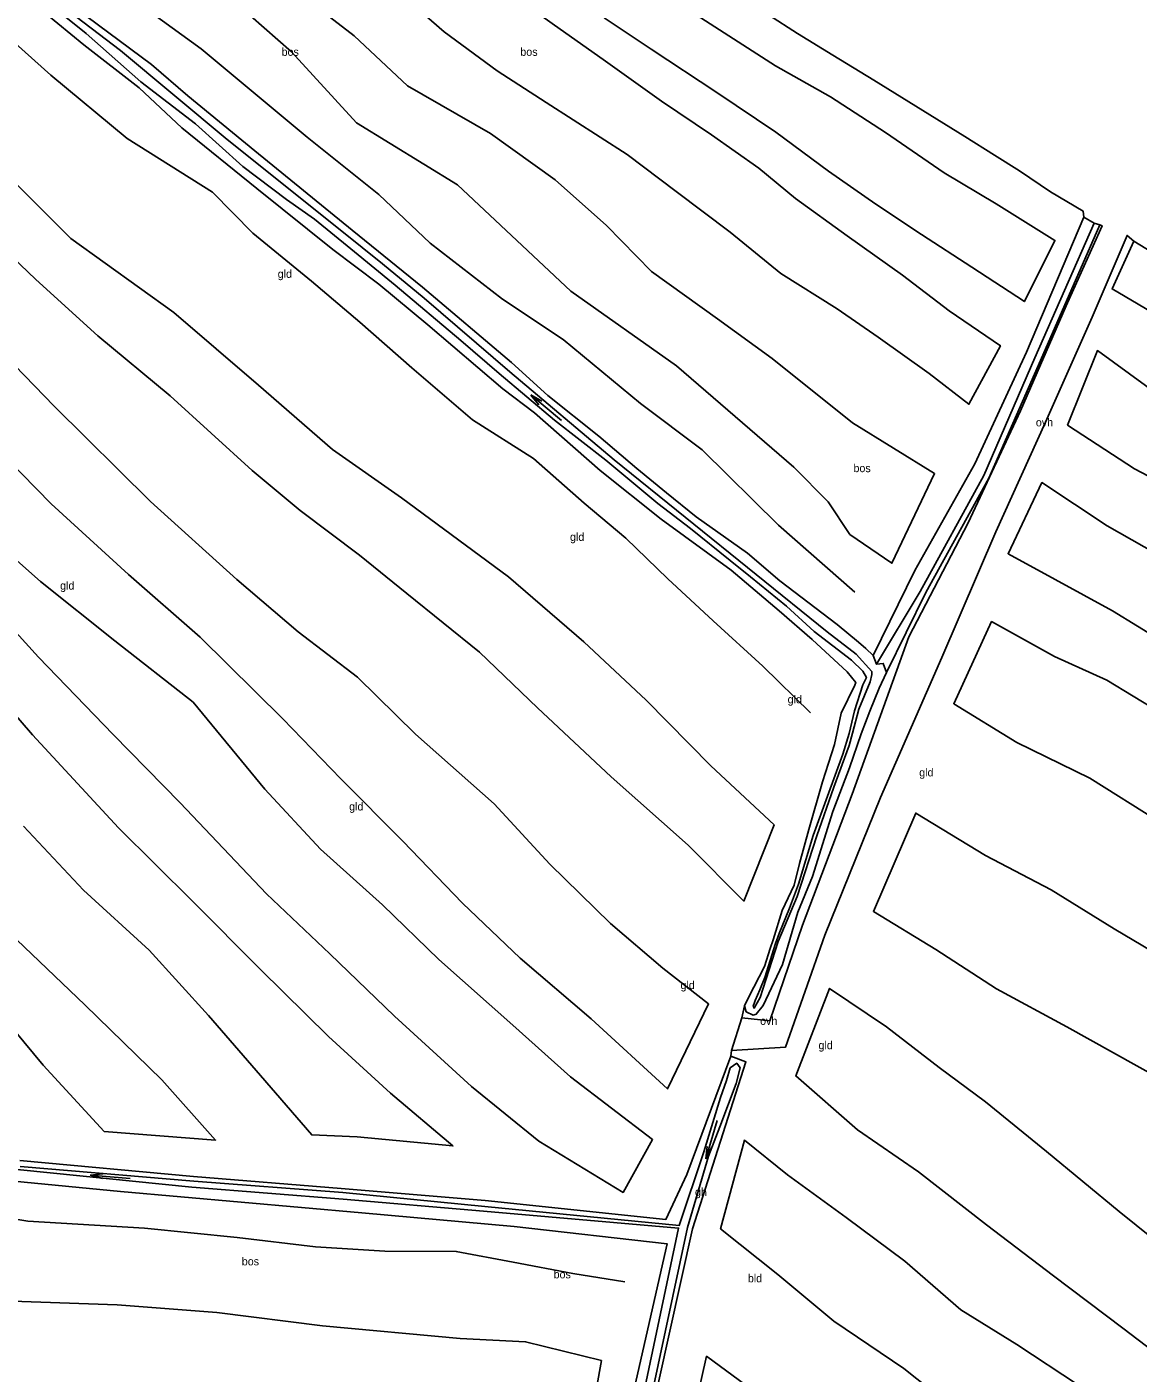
# Model space of a CAD drawing. Extents: x 154825 to 158680, y 370717 to 378075.
# Drawn here: x 155737.7 to 155876.6, y 376911 to 377079.3 of the extents above; entities that cross this region are included whole.
import ezdxf

# ---------------------------------------------------------------- set-up
doc = ezdxf.new("R2010")
doc.units = 0
for name, color, linetype in [('bos(vs)', 7, 'Continuous'), ('bouwland_akkerland(vs)', 7, 'Continuous'), ('breuklijn', 7, 'Continuous'), ('cultuurscheiding', 7, 'Continuous'), ('gashouder punt', 7, 'Continuous'), ('grasland_productiegrasl(vs)', 7, 'Continuous'), ('greppel - midden sloot', 7, 'Continuous'), ('hoogteverschillijn', 7, 'Continuous'), ('insteek sloot', 7, 'Continuous'), ('maaiveldlijn algemeen - onverhard', 7, 'Continuous'), ('onverhard(vs)', 7, 'Continuous'), ('Sloot bodem', 7, 'Continuous'), ('stroomrichting  watergangen', 7, 'Continuous'), ('vlak_akkerland', 7, 'Continuous'), ('vlak_Bos', 7, 'Continuous'), ('vlak_Grasland', 7, 'Continuous'), ('vlak_Grazige_vegetatie', 7, 'Continuous')]:
    doc.layers.add(name, color=color, linetype=linetype)

msp = doc.modelspace()

# ---------------------------------------------------------------- linework, layer by layer
at = {"layer": 'bos(vs)'}
msp.add_lwpolyline([(155869.81, 377055.5), (155862.64, 377038.62), (155856.17, 377024.64), (155848.67, 377011.32), (155843.45, 377000.7)], dxfattribs=at)
at = {"layer": 'breuklijn'}
msp.add_lwpolyline([(155833.53, 377024.24), (155818.9, 377036.91), (155805.68, 377046.23), (155791.49, 377059.51), (155778.9, 377067.29), (155770.76, 377076.15), (155760.52, 377085.18), (155747.44, 377094.53), (155734.38, 377105.71), (155721.14, 377112.94), (155709.6, 377124.17), (155697.1, 377135.78)], dxfattribs=at)
at = {"layer": 'cultuurscheiding'}
for points in [[(155827.37, 376956.92), (155827.05, 376955.41)], [(155825.68, 376950.6), (155825.74, 376951.3)]]:
    msp.add_lwpolyline(points, dxfattribs=at)
at = {"layer": 'greppel - midden sloot'}
msp.add_lwpolyline([(155871.07, 377054.75), (155863.69, 377037.88), (155857.29, 377023.21), (155849.35, 377008.68), (155843.89, 376999.6)], dxfattribs=at)
at = {"layer": 'hoogteverschillijn'}
for points in [[(155697.1, 377135.78), (155691.31, 377130.54), (155696.85, 377125.96), (155701.48, 377121.9), (155706.84, 377117.55), (155713.41, 377111.67), (155721.11, 377105.34), (155731.41, 377097.58), (155740.31, 377090.57), (155748.11, 377084.79), (155759.45, 377076.54), (155772.71, 377065.49), (155781.66, 377058.32), (155788.1, 377052.22), (155797.13, 377045.23), (155804.7, 377040.21), (155814.37, 377032.18), (155822.07, 377026.41), (155831.61, 377016.98), (155841.16, 377008.6)], [(155767.02, 377087.11), (155778.59, 377078.15), (155785.27, 377071.88), (155795.62, 377065.94), (155803.72, 377060.15), (155810.13, 377054.43), (155815.76, 377048.69), (155824.02, 377042.77), (155830.85, 377037.83), (155840.88, 377029.79), (155851.15, 377023.44), (155845.81, 377012.22), (155840.55, 377015.83), (155837.84, 377019.89), (155833.53, 377024.24)], [(155799.45, 377082.46), (155804.35, 377078.99), (155809.73, 377075.17), (155816.99, 377069.97), (155823.24, 377065.77), (155829.16, 377061.62), (155833.77, 377057.8), (155840.22, 377053.13), (155847.15, 377048.23), (155852.98, 377043.79), (155859.36, 377039.41), (155855.43, 377032.09), (155850.48, 377035.95), (155844.09, 377040.47), (155838.98, 377044.02), (155831.93, 377048.43), (155825.6, 377053.6), (155818.85, 377058.71), (155812.73, 377063.33), (155802.59, 377069.82), (155796.48, 377073.78), (155789.83, 377078.64), (155784.46, 377083.35)], [(155835.61, 376993.53), (155829.68, 376999.35), (155823.48, 377005.03), (155817.8, 377010.29), (155812.54, 377015.35), (155807.35, 377019.73), (155801.01, 377025.32), (155793.36, 377030.15), (155785.81, 377036.65), (155779.31, 377042.35), (155773.27, 377047.48), (155765.94, 377053.47), (155760.89, 377058.59), (155750.23, 377065.33), (155740.69, 377073.24), (155732.59, 377080.46)], [(155820.75, 377081.15), (155831.25, 377074.41), (155838.14, 377070.52), (155844.99, 377066.08), (155852.32, 377061.04), (155858.85, 377057.15), (155866.18, 377052.57), (155862.38, 377044.94), (155855.8, 377049.23), (155849.51, 377053.31), (155843.78, 377057.11), (155837.9, 377061.22), (155831.31, 377066.11), (155823.92, 377071.07), (155815.73, 377076.48), (155809.85, 377080.39)], [(155869.7, 377056.25), (155865.65, 377058.65), (155861.75, 377061.26), (155858.65, 377063.23), (155854.93, 377065.56), (155843.54, 377072.61), (155838.44, 377075.73), (155833.99, 377078.46), (155830.39, 377080.78)], [(155735.71, 377060.29), (155743.17, 377052.83), (155756.06, 377043.55), (155766.65, 377034.5), (155775.88, 377026.43), (155784.51, 377020.42), (155797.89, 377010.51), (155807.29, 377002.42), (155815.1, 376995.1), (155823.16, 376986.91), (155831.08, 376979.54), (155827.31, 376969.99), (155820.33, 376976.97), (155810.73, 376985.52), (155801.49, 376994.16), (155794.24, 377001.09), (155785.18, 377008.46), (155779.24, 377013.23), (155771.85, 377018.8), (155765.85, 377023.82), (155755.6, 377033.17), (155746.54, 377040.66), (155738.81, 377047.69), (155731.88, 377054.28)], [(155879.06, 377050.63), (155876.03, 377052.47), (155873.33, 377046.52), (155878.21, 377043.67)], [(155734.93, 377038.24), (155741.1, 377031.86), (155753.11, 377019.93), (155763.92, 377010.19), (155771.59, 377003.65), (155779.02, 376998), (155786.24, 376990.86), (155796.09, 376982.17), (155803.04, 376974.6), (155810.63, 376967.2), (155817.17, 376961.59), (155822.9, 376957.14), (155817.74, 376946.51), (155808.23, 376955.28), (155799.33, 376962.84), (155792.14, 376969.75), (155784.67, 376977.47), (155776.93, 376985.28), (155769.68, 376992.77), (155759.35, 377002.99), (155750.38, 377010.82), (155740.7, 377019.63), (155733.2, 377027.26)], [(155879.49, 377033), (155871.49, 377038.8), (155867.77, 377029.49), (155876.13, 377024.01), (155884.02, 377019.91)], [(155878.86, 377013.4), (155872.7, 377016.9), (155864.55, 377022.3), (155860.32, 377013.42), (155866.21, 377010.19), (155873.37, 377006.29), (155879.62, 377002.46)], [(155732.25, 377016.24), (155739.38, 377009.93), (155748.68, 377002.54), (155758.45, 376994.84), (155767.43, 376983.98), (155774.37, 376976.47), (155782.11, 376969.51), (155789.17, 376962.7), (155798.41, 376954.5), (155805.62, 376948.04), (155815.89, 376940.19), (155812.21, 376933.59), (155801.66, 376939.99), (155793.25, 376946.83), (155783.61, 376955.61), (155775.54, 376963.42), (155767.61, 376970.92), (155756.85, 376982.29), (155748.48, 376990.81), (155739.14, 377000.5), (155730.23, 377010.27)], [(155879.25, 376993.63), (155872.66, 376997.6), (155866.11, 377000.57), (155858.27, 377004.94), (155853.54, 376994.66), (155861.43, 376989.82), (155870.56, 376985.38), (155879.17, 376979.96)], [(155729.32, 377001.24), (155738.37, 376990.76), (155749.13, 376979.15), (155758.4, 376969.99), (155766.88, 376961.46), (155775.4, 376953.05), (155783.15, 376946), (155790.93, 376939.4), (155778.98, 376940.53), (155773.29, 376940.77), (155766.86, 376948.21), (155760.36, 376955.7), (155752.98, 376963.87), (155744.75, 376971.34), (155737.24, 376979.34)], [(155883.21, 376960.83), (155873.58, 376966.54), (155865.73, 376971.4), (155857.49, 376975.7), (155848.78, 376980.99), (155843.49, 376968.71), (155851.31, 376963.95), (155858.88, 376959.02), (155867.66, 376954.27), (155879.33, 376947.79)], [(155735.47, 376966.05), (155744.93, 376957.01), (155754.54, 376947.64), (155761.27, 376940.12), (155747.34, 376941.2), (155739.72, 376949.49), (155732.61, 376957.99)], [(155907.78, 376907.73), (155899.49, 376913.63), (155888.89, 376919.42), (155874.21, 376931.2), (155865.14, 376938.69), (155857.52, 376944.89), (155851.7, 376949.19), (155845.11, 376954.26), (155838.01, 376959.07), (155833.79, 376948.15), (155841.49, 376941.39), (155849.14, 376936.16), (155857.64, 376929.53), (155866.01, 376923.17), (155874.66, 376916.61), (155883.38, 376909.98)], [(155869.11, 376909.47), (155861.42, 376914.58), (155854.44, 376918.9), (155847.41, 376924.97), (155840.1, 376930.44), (155832.77, 376935.79), (155827.36, 376940.1), (155824.39, 376929.03), (155831.55, 376923.31), (155838.56, 376917.48), (155847.28, 376911.58), (155854.99, 376905.45)], [(155812.44, 376922.41), (155805.92, 376923.46), (155798.45, 376924.88), (155791.34, 376926.2), (155782.44, 376926.22), (155773.74, 376926.77), (155763.95, 376927.94), (155752.36, 376929.1), (155737.8, 376930), (155727.39, 376931.69), (155714.44, 376932.41), (155715.02, 376921.27), (155724.5, 376920.22), (155735.85, 376920), (155748.95, 376919.52), (155761.41, 376918.57), (155774.63, 376916.91), (155791.83, 376915.32), (155800.02, 376914.91), (155809.5, 376912.57), (155807.56, 376901.73)], [(155830.7, 376907.17), (155822.64, 376913.11), (155819.68, 376899.92)]]:
    msp.add_lwpolyline(points, dxfattribs=at)
at = {"layer": 'insteek sloot'}
for points in [[(155743.87, 377081.52), (155753.26, 377074.56), (155757.79, 377070.65), (155766.18, 377063.78), (155778.33, 377053.87), (155787.15, 377046.73), (155798.27, 377037.3), (155802.78, 377033.18), (155809.16, 377028.12), (155813.94, 377024.06), (155817.61, 377021.03), (155821.34, 377018.04), (155827.74, 377013.47), (155831.8, 377010.02), (155838.96, 377004.58), (155841.63, 377002.38), (155842.54, 377001.57), (155843.45, 377000.7), (155843.89, 376999.6), (155844.73, 376999.71), (155845.15, 376998.56), (155844.21, 376996.6), (155843.04, 376993.74), (155841.95, 376990.9), (155840.52, 376986.64), (155838.41, 376981.21), (155835.9, 376973.07), (155834.06, 376968.63), (155832.12, 376962.05), (155829.72, 376956.93), (155828.85, 376955.85), (155828.47, 376955.74), (155827.6, 376956.17), (155827.37, 376956.92), (155827.88, 376957.93), (155829.87, 376961.81), (155830.59, 376964.08), (155830.98, 376965.14), (155832.1, 376968.81), (155833.57, 376972), (155834.25, 376974.7), (155835.42, 376978.94), (155837.15, 376984.91), (155838.64, 376989.58), (155839.45, 376993.47), (155841.17, 376996.98), (155841.29, 376997.33), (155840.22, 376998.65), (155835.84, 377002.71), (155831.73, 377006.28), (155825.73, 377011.34), (155816.97, 377017.74), (155809.35, 377023.83), (155801.12, 377031.03), (155797.19, 377034.01), (155787.81, 377042.02), (155781.66, 377047.12), (155775.92, 377051.46), (155766.43, 377059.07), (155757.04, 377066.66), (155751.72, 377071.63), (155744.79, 377077.03), (155738.29, 377082.35)], [(155871.8, 377054.54), (155864.37, 377037.55), (155857.91, 377022.85), (155850.06, 377008.57), (155845.15, 376998.56)], [(155736.8, 376937.56), (155758.52, 376935.55), (155776.96, 376934.08), (155794.97, 376932.55), (155817.55, 376930.2), (155820.17, 376935.81), (155825.68, 376950.6)], [(155951.48, 376912.04), (155950.81, 376910.1), (155944.24, 376887.93), (155932.69, 376850.87), (155927.1, 376832.28), (155925.6, 376832.14), (155908.83, 376834.69), (155899.86, 376836), (155880.29, 376838.49), (155852.58, 376842.4), (155830.69, 376845.17), (155807.49, 376848.44), (155806.69, 376849.7), (155808.97, 376866.31), (155812.21, 376885.55), (155815.22, 376903.44), (155820.87, 376929.02), (155827.55, 376949.9), (155825.68, 376950.6)], [(155710.74, 376938.93), (155711.93, 376937.32), (155749.4, 376933.71), (155779.55, 376931.02), (155798.58, 376929.34), (155817.7, 376927.17), (155811.74, 376900.95), (155807.72, 376874.51), (155804.24, 376845.73)]]:
    msp.add_lwpolyline(points, dxfattribs=at)
at = {"layer": 'maaiveldlijn algemeen - onverhard'}
for points in [[(155872.1, 377054.39), (155867.58, 377044.41), (155861.89, 377031.28), (155855.34, 377017.29), (155847.93, 377003.04), (155840.83, 376983.36), (155834.63, 376966.99), (155830.55, 376955.02), (155827.05, 376955.41)], [(155825.74, 376951.3), (155832.51, 376951.75), (155837.41, 376965.73), (155844.38, 376982.94), (155852.04, 377000.43), (155858.8, 377016.15), (155865.02, 377029.84), (155870.85, 377043), (155875.21, 377053.21)], [(155827.05, 376955.41), (155825.74, 376951.3)]]:
    msp.add_lwpolyline(points, dxfattribs=at)
at = {"layer": 'Sloot bodem'}
for points in [[(155739, 377083.37), (155745.07, 377078.42), (155751.94, 377072.39), (155758.76, 377067.13), (155764.68, 377061.83), (155770.11, 377057.71), (155773.62, 377055.22), (155778.17, 377051.54), (155783.72, 377046.98), (155791.94, 377040.08), (155796.73, 377035.93), (155803.65, 377030.12), (155810.04, 377025.11), (155816.55, 377019.71), (155820.61, 377016.56), (155825.58, 377012.58), (155828.13, 377010.54), (155832.61, 377006.84), (155836.07, 377003.7), (155840.77, 377000.1), (155842.17, 376998.73), (155842.61, 376997.95), (155842.19, 376997.03), (155841.14, 376993.79), (155840.45, 376990.95), (155839.69, 376988.35), (155837.76, 376983.09), (155835.98, 376978.21), (155834.11, 376972.11), (155832.99, 376969.13), (155831.7, 376965.95), (155831.25, 376964.69), (155829.92, 376960.45), (155829.28, 376958.91), (155828.72, 376957.57), (155828.62, 376957.31), (155828.47, 376956.84), (155828.58, 376956.59), (155829.32, 376957.95), (155831.59, 376964.93), (155833.97, 376970.57), (155836.42, 376978.16), (155838.56, 376984.23), (155840.48, 376989.43), (155840.88, 376990.99), (155841.68, 376993.98), (155843.08, 376997.4), (155843.31, 376998.33), (155843.31, 376998.69), (155841.32, 377000.85), (155837.71, 377003.67), (155811.08, 377025.16), (155798.03, 377036.13), (155787.33, 377045.37), (155782.15, 377049.67), (155777.06, 377053.74), (155762.73, 377065.21), (155749.38, 377076.31), (155742.05, 377081.91)], [(155736.82, 376936.83), (155758.55, 376935), (155777.19, 376933.57), (155794.91, 376931.84), (155819.2, 376929.43), (155822.31, 376938.66), (155824.4, 376945.44), (155825.11, 376947.57), (155825.57, 376949.14), (155826.41, 376949.72), (155826.82, 376949.14), (155826.34, 376947.19), (155824.3, 376941.79), (155822.88, 376938.11), (155820.25, 376929.18), (155814.74, 376903.44)], [(155813.8, 376903.84), (155819.14, 376929.12), (155794.75, 376931.23), (155777.21, 376932.74), (155758.29, 376934.24), (155736.87, 376936.39), (155712.89, 376938.59), (155736.78, 376936.4)]]:
    msp.add_lwpolyline(points, dxfattribs=at)
at = {"layer": 'stroomrichting  watergangen'}
for p, q in [((155804.5, 377030.06), (155800.67, 377033.27)), ((155800.67, 377033.27), (155802.04, 377032.48)), ((155800.68, 377033.25), (155801.69, 377032.04)), ((155823.95, 376942.57), (155822.54, 376937.78)), ((155822.54, 376937.78), (155822.71, 376939.34)), ((155822.56, 376937.79), (155823.26, 376939.2)), ((155745.6, 376935.75), (155747.17, 376935.9)), ((155750.57, 376935.34), (155745.6, 376935.75)), ((155745.61, 376935.74), (155747.14, 376935.34))]:
    msp.add_line(p, q, dxfattribs=at)
at = {"layer": 'vlak_akkerland'}
msp.add_lwpolyline([(155815.22, 376903.44), (155820.87, 376929.02), (155827.55, 376949.9), (155825.68, 376950.6), (155825.74, 376951.3), (155832.51, 376951.75), (155837.41, 376965.73), (155844.38, 376982.94), (155852.04, 377000.43), (155858.8, 377016.15), (155865.02, 377029.84), (155870.85, 377043), (155875.21, 377053.21), (155876.03, 377052.47), (155879.06, 377050.63)], dxfattribs=at)
at = {"layer": 'vlak_Bos'}
msp.add_lwpolyline([(155830.39, 377080.78), (155833.99, 377078.46), (155838.44, 377075.73), (155843.54, 377072.61), (155854.93, 377065.56), (155858.65, 377063.23), (155861.75, 377061.26), (155865.65, 377058.65), (155869.7, 377056.25), (155869.81, 377055.5), (155862.64, 377038.62), (155856.17, 377024.64), (155848.67, 377011.32), (155843.45, 377000.7), (155842.54, 377001.57), (155841.63, 377002.38), (155838.96, 377004.58), (155831.8, 377010.02), (155827.74, 377013.47), (155821.34, 377018.04), (155817.61, 377021.03), (155813.94, 377024.06), (155809.16, 377028.12), (155802.78, 377033.18), (155798.27, 377037.3), (155787.15, 377046.73), (155778.33, 377053.87), (155766.18, 377063.78), (155757.79, 377070.65), (155753.26, 377074.56), (155743.87, 377081.52)], dxfattribs=at)
msp.add_lwpolyline([(155804.24, 376845.73), (155803.11, 376845.02), (155762.49, 376851.8), (155749.59, 376852.93), (155738.77, 376855.49), (155731.05, 376858.48), (155721.77, 376865.05), (155715.14, 376871.74), (155711.14, 376878.22), (155709.05, 376884.55), (155707.32, 376891.22), (155707.93, 376894.26), (155711.3, 376903.83), (155710.19, 376916.09), (155709.06, 376926.66), (155707.98, 376936.31), (155710.74, 376938.93), (155711.93, 376937.32), (155749.4, 376933.71), (155779.55, 376931.02), (155798.58, 376929.34), (155817.7, 376927.17), (155811.74, 376900.95), (155807.72, 376874.51)], close=True, dxfattribs=at)
at = {"layer": 'vlak_Grasland'}
msp.add_lwpolyline([(155738.29, 377082.35), (155744.79, 377077.03), (155751.72, 377071.63), (155757.04, 377066.66), (155766.43, 377059.07), (155775.92, 377051.46), (155781.66, 377047.12), (155787.81, 377042.02), (155797.19, 377034.01), (155801.12, 377031.03), (155809.35, 377023.83), (155816.97, 377017.74), (155825.73, 377011.34), (155831.73, 377006.28), (155835.84, 377002.71), (155840.22, 376998.65), (155841.29, 376997.33), (155841.17, 376996.98), (155839.45, 376993.47), (155838.64, 376989.58), (155837.15, 376984.91), (155835.42, 376978.94), (155834.25, 376974.7), (155833.57, 376972), (155832.1, 376968.81), (155830.98, 376965.14), (155830.59, 376964.08), (155829.87, 376961.81), (155827.88, 376957.93), (155827.37, 376956.92), (155827.05, 376955.41), (155825.74, 376951.3), (155825.68, 376950.6), (155820.17, 376935.81), (155817.55, 376930.2), (155794.97, 376932.55), (155776.96, 376934.08), (155758.52, 376935.55), (155736.8, 376937.56)], dxfattribs=at)
at = {"layer": 'vlak_Grazige_vegetatie'}
for points in [[(155739, 377083.37), (155745.07, 377078.42), (155751.94, 377072.39), (155758.76, 377067.13), (155764.68, 377061.83), (155770.11, 377057.71), (155773.62, 377055.22), (155778.17, 377051.54), (155783.72, 377046.98), (155791.94, 377040.08), (155796.73, 377035.93), (155803.65, 377030.12), (155810.04, 377025.11), (155816.55, 377019.71), (155820.61, 377016.56), (155825.58, 377012.58), (155828.13, 377010.54), (155832.61, 377006.84), (155836.07, 377003.7), (155840.77, 377000.1), (155842.17, 376998.73), (155842.61, 376997.95), (155842.19, 376997.03), (155841.14, 376993.79), (155840.45, 376990.95), (155839.69, 376988.35), (155837.76, 376983.09), (155835.98, 376978.21), (155834.11, 376972.11), (155832.99, 376969.13), (155831.7, 376965.95), (155831.25, 376964.69), (155829.92, 376960.45), (155829.28, 376958.91), (155828.72, 376957.57), (155828.62, 376957.31), (155828.47, 376956.84), (155828.58, 376956.59), (155829.32, 376957.95), (155831.59, 376964.93), (155833.97, 376970.57), (155836.42, 376978.16), (155838.56, 376984.23), (155840.48, 376989.43), (155840.88, 376990.99), (155841.68, 376993.98), (155843.08, 376997.4), (155843.31, 376998.33), (155843.31, 376998.69), (155841.32, 377000.85), (155837.71, 377003.67), (155811.08, 377025.16), (155798.03, 377036.13), (155787.33, 377045.37), (155782.15, 377049.67), (155777.06, 377053.74), (155762.73, 377065.21), (155749.38, 377076.31), (155742.05, 377081.91)], [(155743.87, 377081.52), (155753.26, 377074.56), (155757.79, 377070.65), (155766.18, 377063.78), (155778.33, 377053.87), (155787.15, 377046.73), (155798.27, 377037.3), (155802.78, 377033.18), (155809.16, 377028.12), (155813.94, 377024.06), (155817.61, 377021.03), (155821.34, 377018.04), (155827.74, 377013.47), (155831.8, 377010.02), (155838.96, 377004.58), (155841.63, 377002.38), (155842.54, 377001.57), (155843.45, 377000.7), (155843.89, 376999.6), (155844.73, 376999.71), (155845.15, 376998.56), (155844.21, 376996.6), (155843.04, 376993.74), (155841.95, 376990.9), (155840.52, 376986.64), (155838.41, 376981.21), (155835.9, 376973.07), (155834.06, 376968.63), (155832.12, 376962.05), (155829.72, 376956.93), (155828.85, 376955.85), (155828.47, 376955.74), (155827.6, 376956.17), (155827.37, 376956.92), (155827.88, 376957.93), (155829.87, 376961.81), (155830.59, 376964.08), (155830.98, 376965.14), (155832.1, 376968.81), (155833.57, 376972), (155834.25, 376974.7), (155835.42, 376978.94), (155837.15, 376984.91), (155838.64, 376989.58), (155839.45, 376993.47), (155841.17, 376996.98), (155841.29, 376997.33), (155840.22, 376998.65), (155835.84, 377002.71), (155831.73, 377006.28), (155825.73, 377011.34), (155816.97, 377017.74), (155809.35, 377023.83), (155801.12, 377031.03), (155797.19, 377034.01), (155787.81, 377042.02), (155781.66, 377047.12), (155775.92, 377051.46), (155766.43, 377059.07), (155757.04, 377066.66), (155751.72, 377071.63), (155744.79, 377077.03), (155738.29, 377082.35)], [(155736.8, 376937.56), (155758.52, 376935.55), (155776.96, 376934.08), (155794.97, 376932.55), (155817.55, 376930.2), (155820.17, 376935.81), (155825.68, 376950.6), (155827.55, 376949.9), (155820.87, 376929.02), (155815.22, 376903.44)], [(155814.74, 376903.44), (155820.25, 376929.18), (155822.88, 376938.11), (155824.3, 376941.79), (155826.34, 376947.19), (155826.82, 376949.14), (155826.41, 376949.72), (155825.57, 376949.14), (155825.11, 376947.57), (155824.4, 376945.44), (155822.31, 376938.66), (155819.2, 376929.43), (155794.91, 376931.84), (155777.19, 376933.57), (155758.55, 376935), (155736.82, 376936.83)], [(155811.74, 376900.95), (155817.7, 376927.17), (155798.58, 376929.34), (155779.55, 376931.02), (155749.4, 376933.71), (155711.93, 376937.32)], [(155736.87, 376936.39), (155758.29, 376934.24), (155777.21, 376932.74), (155794.75, 376931.23), (155819.14, 376929.12), (155813.8, 376903.84)]]:
    msp.add_lwpolyline(points, dxfattribs=at)
for points in [[(155834.63, 376966.99), (155830.55, 376955.02), (155827.05, 376955.41), (155827.37, 376956.92), (155827.6, 376956.17), (155828.47, 376955.74), (155828.85, 376955.85), (155829.72, 376956.93), (155832.12, 376962.05), (155834.06, 376968.63), (155835.9, 376973.07), (155838.41, 376981.21), (155840.52, 376986.64), (155841.95, 376990.9), (155843.04, 376993.74), (155844.21, 376996.6), (155845.15, 376998.56), (155850.06, 377008.57), (155857.91, 377022.85), (155864.37, 377037.55), (155871.8, 377054.54), (155872.1, 377054.39), (155867.58, 377044.41), (155861.89, 377031.28), (155855.34, 377017.29), (155847.93, 377003.04), (155840.83, 376983.36)], [(155849.35, 377008.68), (155843.89, 376999.6), (155843.45, 377000.7), (155848.67, 377011.32), (155856.17, 377024.64), (155862.64, 377038.62), (155869.81, 377055.5), (155871.07, 377054.75), (155863.69, 377037.88), (155857.29, 377023.21)], [(155850.06, 377008.57), (155845.15, 376998.56), (155844.73, 376999.71), (155843.89, 376999.6), (155849.35, 377008.68), (155857.29, 377023.21), (155863.69, 377037.88), (155871.07, 377054.75), (155871.8, 377054.54), (155864.37, 377037.55), (155857.91, 377022.85)]]:
    msp.add_lwpolyline(points, close=True, dxfattribs=at)

# ---------------------------------------------------------------- texts
at = {"layer": 'bos(vs)'}
for p in [(155769.52, 377075.65), (155799.36, 377075.65), (155841, 377023.61), (155764.54, 376924.46), (155803.52, 376922.84)]:
    msp.add_text('bos', height=1, dxfattribs=at).set_placement(p)
at = {"layer": 'bouwland_akkerland(vs)'}
msp.add_text('bld', height=1, dxfattribs=at).set_placement((155827.8, 376922.35))
at = {"layer": 'gashouder punt'}
msp.add_text('gh', height=1, dxfattribs=at).set_placement((155821.19, 376933.15))
at = {"layer": 'grasland_productiegrasl(vs)'}
for p in [(155769.03, 377047.9), (155805.57, 377015.02), (155741.83, 377008.93), (155832.77, 376994.72), (155849.22, 376985.58), (155777.96, 376981.32), (155819.38, 376958.99), (155836.63, 376951.48)]:
    msp.add_text('gld', height=1, dxfattribs=at).set_placement(p)
at = {"layer": 'onverhard(vs)'}
for p in [(155863.8, 377029.34), (155829.33, 376954.52)]:
    msp.add_text('ovh', height=1, dxfattribs=at).set_placement(p)

doc.saveas('drawing.dxf')
